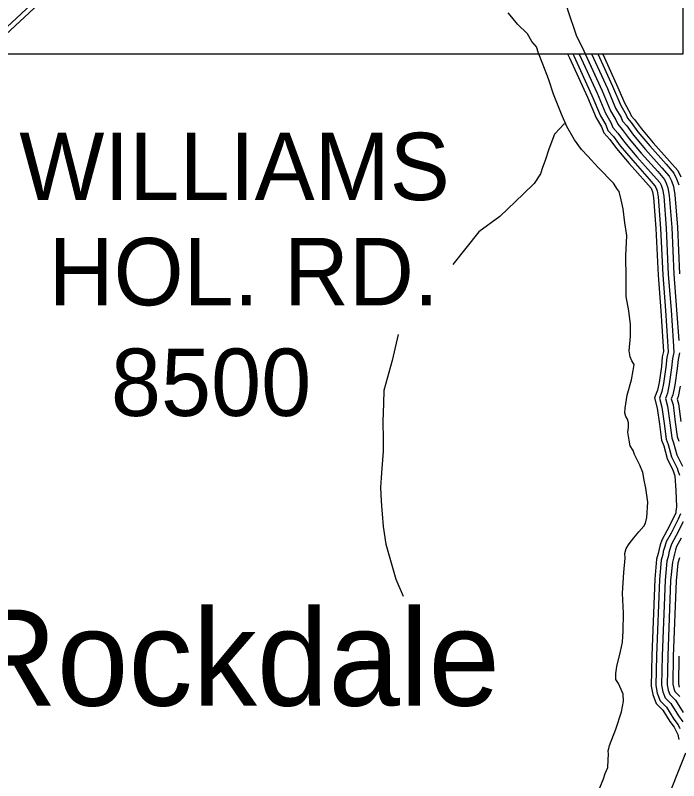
# Model space of a CAD drawing. Extents: x 1551132 to 1791609, y 378168 to 563823.
# Drawn here: x 1597869 to 1601513, y 414761 to 418965 of the extents above; entities that cross this region are included whole.
import ezdxf

# ---------------------------------------------------------------- set-up
doc = ezdxf.new("R2010")
doc.units = 0
for name, color, linetype in [('DESIGN - ROW - Right-of-Way and Easement Labels', 7, 'Continuous'), ('DESIGN - ROW - Right-of-Way Linework', 7, 'Continuous'), ('DESIGN - TRANSPORTATION - Text', 7, 'Continuous'), ('SURVEY - CENTERLINE - Preliminary Text', 7, 'Continuous'), ('SURVEY - PROPERTY - Owners', 7, 'Continuous'), ('SURVEY - TRANSPORTATION - Roads', 7, 'Continuous'), ('SURVEY - VEGETATION - Features with Text', 7, 'Continuous')]:
    doc.layers.add(name, color=color, linetype=linetype)

msp = doc.modelspace()

# ---------------------------------------------------------------- linework, layer by layer
at = {"layer": 'DESIGN - ROW - Right-of-Way Linework'}
msp.add_lwpolyline([(1597488.096, 423032.795), (1597488.093, 418752.857), (1601538.14, 418752.86), (1601538.143, 423032.797), (1597488.096, 423032.795)], dxfattribs=at)
at = {"layer": 'DESIGN - TRANSPORTATION - Text'}
for points in [[(1601194.379, 415469.765), (1601205.179, 415521.691), (1601208.113, 415581.751), (1601209.654, 415681.912), (1601205.338, 415790.173), (1601211.104, 415904.293), (1601218.304, 415982.32), (1601216.713, 416008.396), (1601225.137, 416036.313), (1601241.529, 416062.105), (1601266.028, 416095.79), (1601294.502, 416127.407), (1601320.977, 416159.058), (1601331.218, 416174.925), (1601337.702, 416206.884), (1601343.001, 416290.953), (1601332.193, 416367.264), (1601322.885, 416411.481), (1601315.544, 416453.674), (1601300.178, 416493.984), (1601271.103, 416552.535), (1601263.445, 416574.694), (1601245.862, 416601.02), (1601240.337, 416631.154), (1601233.021, 416675.347), (1601237.421, 416701.331), (1601237.829, 416727.365), (1601232.146, 416747.49), (1601222.371, 416761.666), (1601216.68, 416781.791), (1601219.088, 416807.8), (1601230.163, 416877.76), (1601253.471, 416963.554), (1601262.245, 417013.514), (1601268.762, 417047.473), (1601255.087, 417067.715), (1601247.438, 417089.874), (1601241.938, 417122.017), (1601249.138, 417200.052), (1601248.163, 417266.187), (1601239.346, 417342.456), (1601224.572, 417420.833), (1601224.122, 417521.019), (1601222.022, 417643.272), (1601227.747, 417755.383), (1601216.847, 417825.685), (1601208.031, 417901.954), (1601196.814, 417952.222), (1601185.506, 417996.473), (1601177.706, 418008.615), (1601154.249, 418043.041), (1601071.626, 418128.476), (1601014.635, 418191.47), (1600979.228, 418228.079), (1600940.07, 418280.78), (1600899.221, 418353.54), (1600870.297, 418422.117), (1600826.015, 418530.995), (1600797.341, 418615.589), (1600766.608, 418696.208), (1600743.559, 418756.676), (1600732.092, 418790.919), (1600706.585, 418821.361), (1600683.252, 418863.804), (1600628.112, 418916.747), (1600596.729, 418955.306), (1600577.088, 418977.648)], [(1600890.847, 418368.958), (1600882.164, 418366.682), (1600861.839, 418344.957), (1600831.34, 418311.364), (1600800.09, 418229.704), (1600779.149, 418167.911), (1600764.541, 418128.068), (1600754.025, 418094.167), (1600719.217, 418040.607), (1600660.369, 417983.414), (1600530.53, 417859.194), (1600415.291, 417774.817), (1600272.794, 417595.504)], [(1599973.051, 417212.518), (1599938.66, 417068.898), (1599911.135, 416969.145), (1599894.127, 416903.285), (1599891.044, 416833.208), (1599887.494, 416733.081), (1599889.977, 416634.87), (1599888.986, 416570.768), (1599881.161, 416452.673), (1599878.727, 416424.656), (1599875.919, 416372.604), (1599877.269, 416330.512), (1599880.302, 416268.352), (1599883.652, 416226.226), (1599890.594, 416157.99), (1599905.06, 416059.588), (1599933.451, 415956.969), (1599960.059, 415868.4), (1600000.566, 415773.597)], [(1601070.549, 414700.278), (1601099.64, 414771.963), (1601110.064, 414799.847), (1601124.581, 414833.69), (1601125.231, 414875.758), (1601127.689, 414905.767), (1601126.006, 414925.834), (1601130.189, 414937.793), (1601132.431, 414953.785), (1601167.796, 415043.404), (1601199.262, 415139.09), (1601210.154, 415197.024), (1601208.771, 415237.117), (1601197.154, 415261.343), (1601181.696, 415295.644), (1601168.022, 415315.894), (1601168.547, 415349.945), (1601173.13, 415387.946), (1601194.379, 415469.765)]]:
    msp.add_lwpolyline(points, dxfattribs=at)
at = {"layer": 'SURVEY - CENTERLINE - Preliminary Text'}
for points in [[(1596866.391, 417920.81), (1597077.136, 418155.958), (1597563.4, 418660.071), (1598994.725, 419990.191), (1599486.589, 420397.285), (1599871.822, 420728.294), (1599882.455, 420736.902)], [(1596884.265, 417902.226), (1597095.977, 418138.441), (1597581.416, 418641.713), (1599011.692, 419970.848), (1599503.164, 420377.626), (1599888.297, 420708.543), (1599906.963, 420723.66)]]:
    msp.add_lwpolyline(points, dxfattribs=at)
at = {"layer": 'SURVEY - PROPERTY - Owners'}
msp.add_lwpolyline([(1601549.812, 414912.684), (1601431.223, 414613.284), (1601388.266, 414463.239), (1601379.749, 414437.663), (1601308.234, 414222.907), (1601273.018, 414086.545), (1601245.877, 413962.617), (1601243.044, 413938.075), (1601238.319, 413897.174), (1601231.894, 413829.688), (1601241.119, 413752.345), (1601249.394, 413714.427), (1601261.943, 413653.417), (1601320.325, 413501.355), (1601353.608, 413414.569), (1601384.449, 413334.167), (1601433.956, 413220.756), (1601456.93, 413153.321), (1601468.996, 413075.185), (1601487.779, 412996.717), (1601493.896, 412957.341), (1601509.17, 412858.83), (1601540.578, 412681.083)], dxfattribs=at)
at = {"layer": 'SURVEY - TRANSPORTATION - Roads'}
for points in [[(1600294.487, 420473.371), (1600235.096, 420079.777), (1600207.422, 419841.771), (1600202.655, 419791.753), (1600196.039, 419751.785), (1600203.255, 419701.584), (1600229.963, 419619.023), (1600268.812, 419546.288), (1600315.778, 419481.445), (1600363.151, 419442.644), (1600394.717, 419416.11), (1600444.516, 419405.318), (1600496.29, 419392.501), (1600661.744, 419363.892), (1600695.46, 419347.341), (1600733.093, 419324.716), (1600766.467, 419286.132), (1600827.174, 419205.046), (1600850.415, 419156.603), (1600875.581, 419104.119), (1600903.822, 418991.474), (1600949.704, 418856.529), (1600992.336, 418769.71), (1601000.078, 418752.768)], [(1600903.822, 418991.474), (1600949.704, 418856.529), (1600992.336, 418769.71), (1601092.867, 418549.762), (1601139.149, 418440.843), (1601168.349, 418390.308), (1601177.965, 418366.116), (1601203.506, 418337.665), (1601240.705, 418286.997), (1601307.437, 418207.829), (1601397.801, 418106.243), (1601435.117, 418063.592), (1601444.8, 418043.408), (1601454.392, 418017.215), (1601461.733, 417975.023), (1601474.991, 417798.501), (1601487.041, 417543.853), (1601501.99, 417347.264), (1601513.373, 417178.785)], [(1600902.955, 418752.726), (1600913.063, 418732.134), (1601012.602, 418514.37), (1601060.518, 418401.6), (1601089.2, 418351.957), (1601102.233, 418319.165), (1601135.358, 418282.272), (1601171.74, 418232.712), (1601241.122, 418150.402), (1601332.028, 418048.208), (1601361.219, 418014.849), (1601363.885, 418009.273), (1601369.327, 417994.431), (1601374.585, 417964.189), (1601387.435, 417793.143), (1601399.484, 417538.453), (1601414.5, 417340.981), (1601425.875, 417172.66), (1601429.85, 417117.733), (1601423.025, 417089.041), (1601417.884, 417035.139), (1601405.159, 416947.946), (1601396.317, 416905.419), (1601380.234, 416863.152), (1601395.751, 416807.067), (1601407.517, 416718.506), (1601419.617, 416630.654), (1601431.033, 416599.445), (1601449.407, 416529.818), (1601481.415, 416467.358), (1601484.665, 416457.074), (1601491.256, 416434.69), (1601497.081, 416355.105), (1601500.981, 416264.636), (1601496.54, 416242.119), (1601497.114, 416231.677), (1601486.473, 416207.818), (1601448.799, 416133.249), (1601421.366, 416082.464), (1601411.983, 416055.639), (1601403.25, 416025.396), (1601400.967, 416009.163), (1601391.975, 415977.337), (1601381.45, 415866.992), (1601364.9, 415448.998), (1601362.3, 415281.027), (1601370.967, 415233.834), (1601390.183, 415185.483), (1601425.29, 415149.182), (1601465.106, 415085.355), (1601487.672, 415054.812), (1601496.614, 415036.179), (1601508.497, 415014.195), (1601513.447, 414987.194)], [(1600931.254, 418753.443), (1600936.304, 418743.151), (1601036.135, 418524.745), (1601083.576, 418413.109), (1601112.408, 418363.199), (1601124.441, 418332.932), (1601155.332, 418298.514), (1601191.965, 418248.63), (1601260.563, 418167.236), (1601351.311, 418065.225), (1601382.885, 418029.141), (1601387.61, 418019.282), (1601394.26, 418001.115), (1601400.135, 417967.364), (1601413.101, 417794.709), (1601425.15, 417540.036), (1601440.15, 417342.823), (1601451.524, 417174.452), (1601455.791, 417115.633), (1601448.458, 417084.816), (1601443.416, 417032.056), (1601430.491, 416943.47), (1601421.075, 416898.186), (1601407.267, 416861.885), (1601421.008, 416812.217), (1601433, 416721.956), (1601444.716, 416636.904), (1601455.591, 416607.162), (1601473.565, 416539.068), (1601505.289, 416477.158), (1601509.256, 416464.575), (1601516.706, 416439.316)], [(1600966.237, 418752.243), (1601064.501, 418537.254), (1601111.358, 418426.976), (1601140.374, 418376.758), (1601151.199, 418349.524), (1601179.423, 418318.09), (1601216.331, 418267.813), (1601284.004, 418187.536), (1601374.552, 418085.734), (1601409.001, 418046.366), (1601416.209, 418031.341), (1601424.326, 418009.165), (1601430.934, 417971.197), (1601444.05, 417796.61), (1601456.1, 417541.945), (1601471.074, 417345.048), (1601482.449, 417176.618), (1601487.049, 417113.108), (1601479.107, 417079.732), (1601474.207, 417028.348), (1601461.032, 416938.07), (1601450.924, 416889.469), (1601439.858, 416860.36), (1601451.458, 416818.417), (1601463.724, 416726.106), (1601474.965, 416644.429), (1601485.198, 416616.462), (1601502.681, 416550.227), (1601534.072, 416488.975)], [(1601000.236, 418752.418), (1601092.867, 418549.762), (1601139.149, 418440.843), (1601168.349, 418390.308), (1601177.965, 418366.116), (1601203.506, 418337.665), (1601240.705, 418286.997), (1601307.437, 418207.829), (1601397.801, 418106.243), (1601435.117, 418063.592), (1601444.8, 418043.408), (1601454.392, 418017.215), (1601461.733, 417975.023), (1601474.991, 417798.501), (1601487.041, 417543.853), (1601501.99, 417347.264), (1601513.373, 417178.785)], [(1601034.244, 418752.593), (1601121.233, 418562.271), (1601166.94, 418454.71), (1601196.323, 418403.859), (1601204.731, 418382.708), (1601227.589, 418357.241), (1601265.08, 418306.181), (1601330.87, 418228.121), (1601421.051, 418126.752), (1601461.233, 418080.817), (1601473.391, 418055.475), (1601484.458, 418025.266), (1601492.532, 417978.848), (1601505.932, 417800.393), (1601517.981, 417545.761)], [(1601068.251, 418752.776), (1601149.599, 418574.78), (1601194.723, 418468.577), (1601224.289, 418417.417), (1601231.489, 418399.3), (1601251.68, 418376.816), (1601289.446, 418325.365), (1601354.311, 418248.421), (1601444.292, 418147.26), (1601487.349, 418098.042), (1601501.991, 418067.533), (1601514.524, 418033.316)], [(1601096.2, 418751.059), (1601172.215, 418584.755), (1601216.881, 418479.636), (1601246.597, 418428.218), (1601252.83, 418412.534), (1601270.879, 418392.425), (1601308.879, 418340.665), (1601372.994, 418264.605), (1601462.825, 418163.611), (1601508.174, 418111.785), (1601524.79, 418077.15)], [(1601518.315, 417110.583), (1601509.765, 417074.649), (1601504.99, 417024.631), (1601491.573, 416932.67), (1601480.774, 416880.744), (1601472.44, 416858.835), (1601481.907, 416824.626), (1601494.44, 416730.265), (1601505.223, 416651.954), (1601514.806, 416625.762)], [(1601518.315, 417110.583), (1601509.765, 417074.649), (1601504.99, 417024.631), (1601491.573, 416932.67), (1601480.774, 416880.744), (1601472.44, 416858.835), (1601481.907, 416824.626), (1601494.44, 416730.265), (1601505.223, 416651.954), (1601514.806, 416625.762)], [(1601522.114, 416927.27), (1601510.623, 416872.019), (1601505.023, 416857.31), (1601512.356, 416830.834), (1601525.156, 416734.423)], [(1601523.139, 416226.893), (1601509.706, 416196.776), (1601471.598, 416121.341), (1601444.966, 416072.039), (1601436.491, 416047.814), (1601428.466, 416020.013), (1601426.191, 416003.846), (1601417.358, 415972.578), (1601407.116, 415865.259), (1601390.608, 415448.289), (1601388.058, 415283.168), (1601395.8, 415240.976), (1601412.207, 415199.708), (1601445.673, 415165.107), (1601486.389, 415099.822), (1601509.805, 415068.13), (1601519.53, 415047.862)], [(1601537.714, 416183.459), (1601499.073, 416106.973), (1601473.407, 416059.481), (1601466.04, 416038.397), (1601458.857, 416013.521), (1601456.59, 415997.446), (1601447.949, 415966.845), (1601438.057, 415863.167), (1601421.599, 415447.431), (1601419.099, 415285.752), (1601425.732, 415249.584), (1601438.749, 415216.85), (1601470.231, 415184.299), (1601512.047, 415117.264), (1601536.48, 415084.188)], [(1601526.547, 416092.615), (1601501.856, 416046.914), (1601495.581, 416028.971), (1601489.248, 416007.029), (1601486.998, 415991.037), (1601478.54, 415961.111), (1601468.998, 415861.084), (1601452.59, 415446.581), (1601450.14, 415288.335), (1601455.673, 415258.193), (1601465.29, 415234.001), (1601494.797, 415203.491), (1601537.705, 415134.706)], [(1601526.547, 416092.615), (1601501.856, 416046.914), (1601495.581, 416028.971), (1601489.248, 416007.029), (1601486.998, 415991.037), (1601478.54, 415961.111), (1601468.998, 415861.084), (1601452.59, 415446.581), (1601450.14, 415288.335), (1601455.673, 415258.193), (1601465.29, 415234.001), (1601494.797, 415203.491), (1601537.705, 415134.706)], [(1601517.406, 415984.629), (1601509.131, 415955.378), (1601499.939, 415859), (1601483.581, 415445.731), (1601481.181, 415290.919), (1601485.614, 415266.801), (1601491.831, 415251.151), (1601519.363, 415222.684)], [(1601514.572, 415444.873), (1601512.222, 415293.502), (1601515.547, 415275.41)]]:
    msp.add_lwpolyline(points, dxfattribs=at)

# ---------------------------------------------------------------- texts
at = {"layer": 'DESIGN - ROW - Right-of-Way and Easement Labels'}
for s, p in [('WILLIAMS', (1597891.358, 417949.82)), ('HOL. RD.', (1598051.796, 417371.988)), ('8500', (1598394.104, 416764.372))]:
    msp.add_text(s, height=369.9913, rotation=0.000036, dxfattribs=at).set_placement(p)
at = {"layer": 'SURVEY - VEGETATION - Features with Text'}
msp.add_text('Rockdale', height=527.9876, rotation=0.000036, dxfattribs=at).set_placement((1597587.872, 415173.021))

doc.saveas('drawing.dxf')
